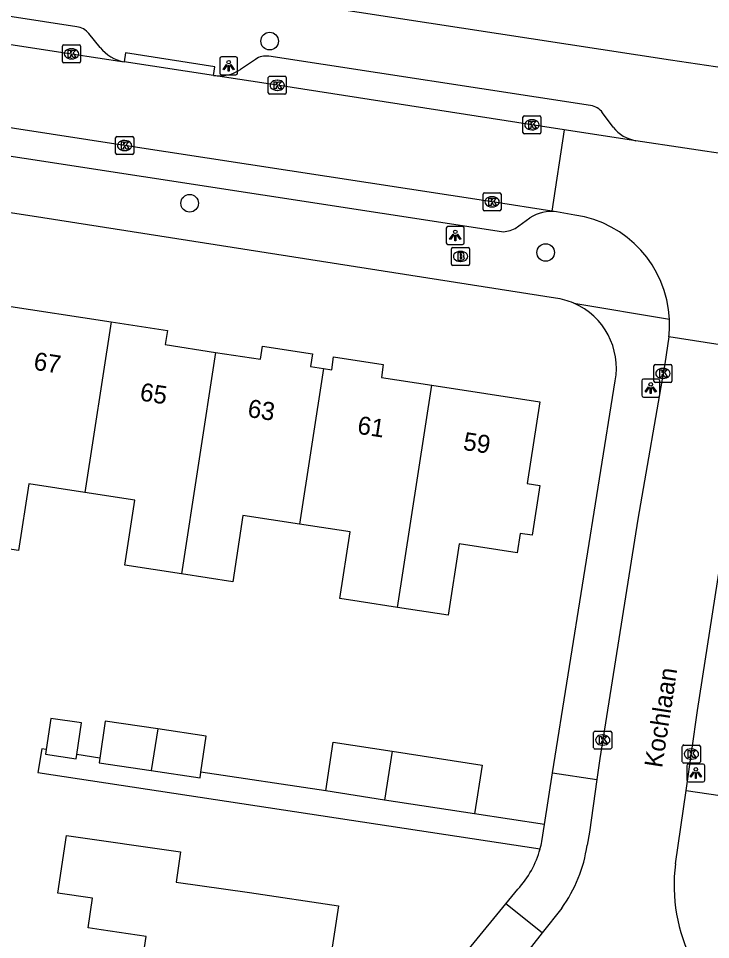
# Model space of a CAD drawing. Extents: x 161486 to 162249, y 379484 to 380829.
# Drawn here: x 161884.6 to 161923, y 380504.4 to 380555.5 of the extents above; entities that cross this region are included whole.
import ezdxf

# ---------------------------------------------------------------- set-up
doc = ezdxf.new("R2010")
doc.units = 0
for name, color, linetype in [('IMGEO_Boom', 7, 'Continuous'), ('IMGEO_Brandkraan', 7, 'Continuous'), ('IMGEO_Kolk', 7, 'Continuous'), ('IMGEO_Lichtpunt', 7, 'Continuous'), ('IMGEO_Openbare_ruimte_label', 7, 'Continuous'), ('IMGEO_Pand', 7, 'Continuous'), ('IMGEO_Pand_nummerreeks', 7, 'Continuous'), ('IMGEO_Rijbaan_lokaal_open', 7, 'Continuous'), ('IMGEO_Voetpad_open', 7, 'Continuous')]:
    doc.layers.add(name, color=color, linetype=linetype)

msp = doc.modelspace()

# ---------------------------------------------------------------- linework, layer by layer
at = {"layer": 'IMGEO_Boom'}
for centre in [(161898.494, 380554.242), (161894.054, 380545.25), (161913.812, 380542.518)]:
    msp.add_circle(centre, 0.489, dxfattribs=at)
at = {"layer": 'IMGEO_Brandkraan'}
for p, q in [((161908.589, 380541.876), (161908.589, 380542.728)), ((161908.664, 380542.802), (161909.516, 380542.802)), ((161909.077, 380542.582), (161909.102, 380542.582)), ((161909.59, 380542.728), (161909.59, 380541.876)), ((161909.516, 380541.802), (161908.664, 380541.802)), ((161909.1, 380542.022), (161909.075, 380542.022))]:
    msp.add_line(p, q, dxfattribs=at)
for points in [[(161908.589, 380541.876), (161908.589, 380542.728)], [(161908.664, 380542.802), (161909.516, 380542.802)], [(161909.59, 380542.728), (161909.59, 380541.876)], [(161908.937, 380542.502), (161908.937, 380542.102), (161909.15, 380542.102)], [(161909.168, 380542.502), (161908.937, 380542.502)], [(161909.116, 380542.421), (161909.062, 380542.421), (161909.062, 380542.345)], [(161909.062, 380542.345), (161909.115, 380542.345)], [(161909.124, 380542.269), (161909.062, 380542.269), (161909.062, 380542.188)], [(161909.062, 380542.188), (161909.124, 380542.188)], [(161909.516, 380541.802), (161908.664, 380541.802)]]:
    msp.add_lwpolyline(points, dxfattribs=at)
for centre, radius, start, end in [((161908.666, 380542.726), 0.0765, 91.552, 178.448), ((161908.666, 380542.726), 0.0765, 91.552, 178.448), ((161909.514, 380542.726), 0.0765, 1.552, 88.448), ((161909.514, 380542.726), 0.0765, 1.552, 88.448), ((161909.117, 380542.383), 0.0379, 267.8285, 90.9355), ((161909.125, 380542.228), 0.0404, 269.8759, 90.5077), ((161909.156, 380542.353), 0.251, 268.6676, 293.5347), ((161909.172, 380542.357), 0.145, 59.4692, 91.5367), ((161909.197, 380542.404), 0.0922, 285.5137, 58.1501), ((161909.202, 380542.212), 0.105, 301.3115, 78.989), ((161908.666, 380541.878), 0.0765, 181.552, 268.448), ((161908.666, 380541.878), 0.0765, 181.552, 268.448), ((161909.514, 380541.878), 0.0765, 271.552, 358.448), ((161909.514, 380541.878), 0.0765, 271.552, 358.448)]:
    msp.add_arc(centre, radius, start, end, dxfattribs=at)
for centre, major_axis, ratio, start_param, end_param in [((161909.076, 380542.302), (-0.387, 0.002), 0.722429, 4.712389, 7.853982), ((161909.101, 380542.302), (-0.39, 0.002), 0.717154, 1.570796, 4.712389)]:
    msp.add_ellipse(centre, major_axis=major_axis, ratio=ratio, start_param=start_param, end_param=end_param, dxfattribs=at)
at = {"layer": 'IMGEO_Kolk'}
for p, q in [((161886.998, 380553.111), (161886.998, 380553.963)), ((161887.073, 380554.037), (161887.925, 380554.037)), ((161887.486, 380553.817), (161887.511, 380553.817)), ((161887.999, 380553.963), (161887.999, 380553.111)), ((161887.925, 380553.037), (161887.073, 380553.037)), ((161887.509, 380553.257), (161887.484, 380553.257)), ((161898.493, 380552.292), (161899.345, 380552.292)), ((161898.418, 380551.366), (161898.418, 380552.218)), ((161898.906, 380552.072), (161898.931, 380552.072)), ((161899.419, 380552.218), (161899.419, 380551.366)), ((161899.345, 380551.292), (161898.493, 380551.292)), ((161898.929, 380551.512), (161898.904, 380551.512)), ((161912.551, 380549.175), (161912.551, 380550.027)), ((161912.626, 380550.101), (161913.478, 380550.101)), ((161913.039, 380549.881), (161913.064, 380549.881)), ((161913.552, 380550.027), (161913.552, 380549.175)), ((161913.062, 380549.321), (161913.037, 380549.321)), ((161889.947, 380548.025), (161889.947, 380548.877)), ((161890.022, 380548.951), (161890.874, 380548.951)), ((161890.435, 380548.731), (161890.46, 380548.731)), ((161890.948, 380548.877), (161890.948, 380548.025)), ((161913.478, 380549.101), (161912.626, 380549.101)), ((161890.458, 380548.171), (161890.433, 380548.171)), ((161890.874, 380547.951), (161890.022, 380547.951)), ((161910.336, 380544.903), (161910.336, 380545.755)), ((161910.411, 380545.829), (161911.263, 380545.829)), ((161911.337, 380545.755), (161911.337, 380544.903)), ((161910.824, 380545.609), (161910.849, 380545.609)), ((161911.263, 380544.829), (161910.411, 380544.829)), ((161910.847, 380545.049), (161910.822, 380545.049)), ((161919.822, 380535.384), (161919.822, 380536.236)), ((161919.897, 380536.31), (161920.749, 380536.31)), ((161920.31, 380536.09), (161920.335, 380536.09)), ((161920.823, 380536.236), (161920.823, 380535.384)), ((161920.333, 380535.53), (161920.308, 380535.53)), ((161920.749, 380535.31), (161919.897, 380535.31)), ((161916.477, 380515.053), (161916.477, 380515.905)), ((161916.552, 380515.979), (161917.404, 380515.979)), ((161916.965, 380515.759), (161916.99, 380515.759)), ((161917.478, 380515.905), (161917.478, 380515.053)), ((161917.404, 380514.979), (161916.552, 380514.979)), ((161916.988, 380515.199), (161916.963, 380515.199)), ((161921.398, 380514.277), (161921.398, 380515.129)), ((161921.473, 380515.203), (161922.325, 380515.203)), ((161921.886, 380514.983), (161921.911, 380514.983)), ((161922.399, 380515.129), (161922.399, 380514.277)), ((161922.325, 380514.203), (161921.473, 380514.203)), ((161921.909, 380514.423), (161921.884, 380514.423))]:
    msp.add_line(p, q, dxfattribs=at)
for points in [[(161886.998, 380553.111), (161886.998, 380553.963)], [(161887.073, 380554.037), (161887.925, 380554.037)], [(161887.999, 380553.963), (161887.999, 380553.111)], [(161887.319, 380553.737), (161887.442, 380553.737), (161887.442, 380553.586), (161887.572, 380553.737), (161887.736, 380553.737), (161887.59, 380553.586), (161887.743, 380553.337), (161887.591, 380553.337), (161887.506, 380553.501), (161887.442, 380553.434), (161887.442, 380553.337), (161887.319, 380553.337), (161887.319, 380553.737)], [(161887.925, 380553.037), (161887.073, 380553.037)], [(161898.493, 380552.292), (161899.345, 380552.292)], [(161898.418, 380551.366), (161898.418, 380552.218)], [(161898.739, 380551.992), (161898.862, 380551.992), (161898.862, 380551.841), (161898.992, 380551.992), (161899.156, 380551.992), (161899.01, 380551.841), (161899.163, 380551.592), (161899.011, 380551.592), (161898.926, 380551.756), (161898.862, 380551.689), (161898.862, 380551.592), (161898.739, 380551.592), (161898.739, 380551.992)], [(161899.419, 380552.218), (161899.419, 380551.366)], [(161899.345, 380551.292), (161898.493, 380551.292)], [(161912.551, 380549.175), (161912.551, 380550.027)], [(161912.626, 380550.101), (161913.478, 380550.101)], [(161912.872, 380549.801), (161912.995, 380549.801), (161912.995, 380549.65), (161913.125, 380549.801), (161913.289, 380549.801), (161913.143, 380549.65), (161913.296, 380549.401), (161913.144, 380549.401), (161913.059, 380549.565), (161912.995, 380549.498), (161912.995, 380549.401), (161912.872, 380549.401), (161912.872, 380549.801)], [(161913.552, 380550.027), (161913.552, 380549.175)], [(161889.947, 380548.025), (161889.947, 380548.877)], [(161890.022, 380548.951), (161890.874, 380548.951)], [(161890.948, 380548.877), (161890.948, 380548.025)], [(161913.478, 380549.101), (161912.626, 380549.101)], [(161890.268, 380548.651), (161890.391, 380548.651), (161890.391, 380548.5), (161890.521, 380548.651), (161890.685, 380548.651), (161890.539, 380548.5), (161890.692, 380548.251), (161890.54, 380548.251), (161890.455, 380548.415), (161890.391, 380548.348), (161890.391, 380548.251), (161890.268, 380548.251), (161890.268, 380548.651)], [(161890.874, 380547.951), (161890.022, 380547.951)], [(161910.336, 380544.903), (161910.336, 380545.755)], [(161910.411, 380545.829), (161911.263, 380545.829)], [(161911.337, 380545.755), (161911.337, 380544.903)], [(161910.657, 380545.529), (161910.78, 380545.529), (161910.78, 380545.378), (161910.91, 380545.529), (161911.074, 380545.529), (161910.928, 380545.378), (161911.081, 380545.129), (161910.929, 380545.129), (161910.844, 380545.293), (161910.78, 380545.226), (161910.78, 380545.129), (161910.657, 380545.129), (161910.657, 380545.529)], [(161911.263, 380544.829), (161910.411, 380544.829)], [(161919.822, 380535.384), (161919.822, 380536.236)], [(161919.897, 380536.31), (161920.749, 380536.31)], [(161920.143, 380536.01), (161920.266, 380536.01), (161920.266, 380535.859), (161920.396, 380536.01), (161920.56, 380536.01), (161920.414, 380535.859), (161920.567, 380535.61), (161920.415, 380535.61), (161920.33, 380535.774), (161920.266, 380535.707), (161920.266, 380535.61), (161920.143, 380535.61), (161920.143, 380536.01)], [(161920.823, 380536.236), (161920.823, 380535.384)], [(161920.749, 380535.31), (161919.897, 380535.31)], [(161916.477, 380515.053), (161916.477, 380515.905)], [(161916.552, 380515.979), (161917.404, 380515.979)], [(161916.798, 380515.679), (161916.921, 380515.679), (161916.921, 380515.528), (161917.051, 380515.679), (161917.215, 380515.679), (161917.069, 380515.528), (161917.222, 380515.279), (161917.07, 380515.279), (161916.985, 380515.443), (161916.921, 380515.376), (161916.921, 380515.279), (161916.798, 380515.279), (161916.798, 380515.679)], [(161917.478, 380515.905), (161917.478, 380515.053)], [(161917.404, 380514.979), (161916.552, 380514.979)], [(161921.398, 380514.277), (161921.398, 380515.129)], [(161921.473, 380515.203), (161922.325, 380515.203)], [(161922.399, 380515.129), (161922.399, 380514.277)], [(161921.719, 380514.903), (161921.842, 380514.903), (161921.842, 380514.752), (161921.972, 380514.903), (161922.136, 380514.903), (161921.99, 380514.752), (161922.143, 380514.503), (161921.991, 380514.503), (161921.906, 380514.667), (161921.842, 380514.6), (161921.842, 380514.503), (161921.719, 380514.503), (161921.719, 380514.903)], [(161922.325, 380514.203), (161921.473, 380514.203)]]:
    msp.add_lwpolyline(points, dxfattribs=at)
for centre, start, end in [((161887.075, 380553.961), 91.552, 178.448), ((161887.075, 380553.961), 91.552, 178.448), ((161887.923, 380553.961), 1.552, 88.448), ((161887.923, 380553.961), 1.552, 88.448), ((161887.075, 380553.113), 181.552, 268.448), ((161887.075, 380553.113), 181.552, 268.448), ((161887.923, 380553.113), 271.552, 358.448), ((161887.923, 380553.113), 271.552, 358.448), ((161898.495, 380552.216), 91.552, 178.448), ((161898.495, 380552.216), 91.552, 178.448), ((161899.343, 380552.216), 1.552, 88.448), ((161899.343, 380552.216), 1.552, 88.448), ((161898.495, 380551.368), 181.552, 268.448), ((161898.495, 380551.368), 181.552, 268.448), ((161899.343, 380551.368), 271.552, 358.448), ((161899.343, 380551.368), 271.552, 358.448), ((161912.628, 380550.025), 91.552, 178.448), ((161912.628, 380550.025), 91.552, 178.448), ((161913.476, 380550.025), 1.552, 88.448), ((161913.476, 380550.025), 1.552, 88.448), ((161890.024, 380548.875), 91.552, 178.448), ((161890.024, 380548.875), 91.552, 178.448), ((161890.872, 380548.875), 1.552, 88.448), ((161890.872, 380548.875), 1.552, 88.448), ((161912.628, 380549.177), 181.552, 268.448), ((161912.628, 380549.177), 181.552, 268.448), ((161913.476, 380549.177), 271.552, 358.448), ((161913.476, 380549.177), 271.552, 358.448), ((161890.024, 380548.027), 181.552, 268.448), ((161890.024, 380548.027), 181.552, 268.448), ((161890.872, 380548.027), 271.552, 358.448), ((161890.872, 380548.027), 271.552, 358.448), ((161910.413, 380545.753), 91.552, 178.448), ((161910.413, 380545.753), 91.552, 178.448), ((161911.261, 380545.753), 1.552, 88.448), ((161911.261, 380545.753), 1.552, 88.448), ((161910.413, 380544.905), 181.552, 268.448), ((161910.413, 380544.905), 181.552, 268.448), ((161911.261, 380544.905), 271.552, 358.448), ((161911.261, 380544.905), 271.552, 358.448), ((161919.899, 380536.234), 91.552, 178.448), ((161919.899, 380536.234), 91.552, 178.448), ((161920.747, 380536.234), 1.552, 88.448), ((161920.747, 380536.234), 1.552, 88.448), ((161919.899, 380535.386), 181.552, 268.448), ((161919.899, 380535.386), 181.552, 268.448), ((161920.747, 380535.386), 271.552, 358.448), ((161920.747, 380535.386), 271.552, 358.448), ((161916.554, 380515.903), 91.552, 178.448), ((161916.554, 380515.903), 91.552, 178.448), ((161917.402, 380515.903), 1.552, 88.448), ((161917.402, 380515.903), 1.552, 88.448), ((161916.554, 380515.055), 181.552, 268.448), ((161916.554, 380515.055), 181.552, 268.448), ((161917.402, 380515.055), 271.552, 358.448), ((161917.402, 380515.055), 271.552, 358.448), ((161921.475, 380515.127), 91.552, 178.448), ((161921.475, 380515.127), 91.552, 178.448), ((161922.323, 380515.127), 1.552, 88.448), ((161922.323, 380515.127), 1.552, 88.448), ((161921.475, 380514.279), 181.552, 268.448), ((161921.475, 380514.279), 181.552, 268.448), ((161922.323, 380514.279), 271.552, 358.448), ((161922.323, 380514.279), 271.552, 358.448)]:
    msp.add_arc(centre, 0.0765, start, end, dxfattribs=at)
for centre, major_axis, ratio, start_param, end_param in [((161887.485, 380553.537), (-0.387, 0.002), 0.722429, 4.712389, 7.853982), ((161887.51, 380553.537), (-0.39, 0.002), 0.717154, 1.570796, 4.712389), ((161898.905, 380551.792), (-0.387, 0.002), 0.722429, 4.712389, 7.853982), ((161898.93, 380551.792), (-0.39, 0.002), 0.717154, 1.570796, 4.712389), ((161913.038, 380549.601), (-0.387, 0.002), 0.722429, 4.712389, 7.853982), ((161913.063, 380549.601), (-0.39, 0.002), 0.717154, 1.570796, 4.712389), ((161890.434, 380548.451), (-0.387, 0.002), 0.722429, 4.712389, 7.853982), ((161890.459, 380548.451), (-0.39, 0.002), 0.717154, 1.570796, 4.712389), ((161910.823, 380545.329), (-0.387, 0.002), 0.722429, 4.712389, 7.853982), ((161910.848, 380545.329), (-0.39, 0.002), 0.717154, 1.570796, 4.712389), ((161920.309, 380535.81), (-0.387, 0.002), 0.722429, 4.712389, 7.853982), ((161920.334, 380535.81), (-0.39, 0.002), 0.717154, 1.570796, 4.712389), ((161916.964, 380515.479), (-0.387, 0.002), 0.722429, 4.712389, 7.853982), ((161916.989, 380515.479), (-0.39, 0.002), 0.717154, 1.570796, 4.712389), ((161921.885, 380514.703), (-0.387, 0.002), 0.722429, 4.712389, 7.853982), ((161921.91, 380514.703), (-0.39, 0.002), 0.717154, 1.570796, 4.712389)]:
    msp.add_ellipse(centre, major_axis=major_axis, ratio=ratio, start_param=start_param, end_param=end_param, dxfattribs=at)
at = {"layer": 'IMGEO_Lichtpunt'}
for p, q in [((161896.625, 380553.37), (161895.817, 380553.37)), ((161896.625, 380553.37), (161895.817, 380553.37)), ((161895.723, 380553.275), (161895.723, 380552.468)), ((161895.723, 380553.275), (161895.723, 380552.468)), ((161896.719, 380552.468), (161896.719, 380553.275)), ((161896.719, 380552.468), (161896.719, 380553.275)), ((161895.817, 380552.374), (161896.625, 380552.374)), ((161895.817, 380552.374), (161896.625, 380552.374)), ((161908.298, 380543.865), (161908.298, 380543.058)), ((161908.298, 380543.865), (161908.298, 380543.058)), ((161909.2, 380543.96), (161908.392, 380543.96)), ((161909.2, 380543.96), (161908.392, 380543.96)), ((161909.294, 380543.058), (161909.294, 380543.865)), ((161909.294, 380543.058), (161909.294, 380543.865)), ((161908.392, 380542.964), (161909.2, 380542.964)), ((161908.392, 380542.964), (161909.2, 380542.964)), ((161919.146, 380535.405), (161919.146, 380534.598)), ((161919.146, 380535.405), (161919.146, 380534.598)), ((161920.048, 380535.5), (161919.24, 380535.5)), ((161920.048, 380535.5), (161919.24, 380535.5)), ((161920.142, 380534.598), (161920.142, 380535.405)), ((161920.142, 380534.598), (161920.142, 380535.405)), ((161919.24, 380534.504), (161920.048, 380534.504)), ((161919.24, 380534.504), (161920.048, 380534.504)), ((161921.647, 380514.053), (161921.647, 380513.246)), ((161921.647, 380514.053), (161921.647, 380513.246)), ((161922.549, 380514.148), (161921.741, 380514.148)), ((161922.549, 380514.148), (161921.741, 380514.148)), ((161922.643, 380513.246), (161922.643, 380514.053)), ((161922.643, 380513.246), (161922.643, 380514.053)), ((161921.741, 380513.152), (161922.549, 380513.152)), ((161921.741, 380513.152), (161922.549, 380513.152))]:
    msp.add_line(p, q, dxfattribs=at)
for points in [[(161896.097, 380552.939), (161896.136, 380552.911), (161895.948, 380552.649), (161895.91, 380552.676), (161896.097, 380552.939)], [(161896.199, 380552.891), (161896.246, 380552.891), (161896.246, 380552.569), (161896.199, 380552.569), (161896.199, 380552.891)], [(161896.309, 380552.911), (161896.347, 380552.938), (161896.534, 380552.676), (161896.495, 380552.648), (161896.309, 380552.911)], [(161908.672, 380543.529), (161908.711, 380543.501), (161908.523, 380543.239), (161908.485, 380543.266), (161908.672, 380543.529)], [(161908.774, 380543.481), (161908.821, 380543.481), (161908.821, 380543.159), (161908.774, 380543.159), (161908.774, 380543.481)], [(161908.884, 380543.501), (161908.922, 380543.528), (161909.109, 380543.266), (161909.07, 380543.238), (161908.884, 380543.501)], [(161919.52, 380535.069), (161919.559, 380535.041), (161919.371, 380534.779), (161919.333, 380534.806), (161919.52, 380535.069)], [(161919.622, 380535.021), (161919.669, 380535.021), (161919.669, 380534.699), (161919.622, 380534.699), (161919.622, 380535.021)], [(161919.732, 380535.041), (161919.77, 380535.068), (161919.957, 380534.806), (161919.918, 380534.778), (161919.732, 380535.041)], [(161922.021, 380513.717), (161922.06, 380513.689), (161921.872, 380513.427), (161921.834, 380513.454), (161922.021, 380513.717)], [(161922.123, 380513.669), (161922.17, 380513.669), (161922.17, 380513.347), (161922.123, 380513.347), (161922.123, 380513.669)], [(161922.233, 380513.689), (161922.271, 380513.716), (161922.458, 380513.454), (161922.419, 380513.426), (161922.233, 380513.689)]]:
    msp.add_lwpolyline(points, dxfattribs=at)
for centre in [(161896.222, 380553.073), (161908.797, 380543.663), (161919.645, 380535.203), (161922.146, 380513.851)]:
    msp.add_circle(centre, 0.0994, dxfattribs=at)
for centre, start, end in [((161895.817, 380553.275), 90, 180), ((161895.817, 380553.275), 90, 180), ((161896.625, 380553.275), 0, 90), ((161896.625, 380553.275), 0, 90), ((161895.817, 380552.468), 180, 270), ((161895.817, 380552.468), 180, 270), ((161896.625, 380552.468), 270, 0), ((161896.625, 380552.468), 270, 360), ((161908.392, 380543.865), 90, 180), ((161908.392, 380543.865), 90, 180), ((161909.2, 380543.865), 0, 90), ((161909.2, 380543.865), 0, 90), ((161908.392, 380543.058), 180, 270), ((161908.392, 380543.058), 180, 270), ((161909.2, 380543.058), 270, 0), ((161909.2, 380543.058), 270, 360), ((161919.24, 380535.405), 90, 180), ((161919.24, 380535.405), 90, 180), ((161920.048, 380535.405), 0, 90), ((161920.048, 380535.405), 0, 90), ((161919.24, 380534.598), 180, 270), ((161919.24, 380534.598), 180, 270), ((161920.048, 380534.598), 270, 0), ((161920.048, 380534.598), 270, 360), ((161921.741, 380514.053), 90, 180), ((161921.741, 380514.053), 90, 180), ((161922.549, 380514.053), 0, 90), ((161922.549, 380514.053), 0, 90), ((161921.741, 380513.246), 180, 270), ((161921.741, 380513.246), 180, 270), ((161922.549, 380513.246), 270, 0), ((161922.549, 380513.246), 270, 360)]:
    msp.add_arc(centre, 0.0946, start, end, dxfattribs=at)
at = {"layer": 'IMGEO_Pand'}
for points in [[(161883.646, 380539.603), (161889.692, 380538.674)], [(161889.692, 380538.674), (161888.236, 380529.203)], [(161889.692, 380538.674), (161892.825, 380538.192), (161892.705, 380537.408), (161895.495, 380536.979)], [(161895.495, 380536.979), (161893.606, 380524.696)], [(161895.495, 380536.979), (161897.993, 380536.595), (161898.106, 380537.327), (161900.867, 380536.903), (161900.758, 380536.196), (161901.484, 380536.085)], [(161901.484, 380536.085), (161901.937, 380536.015), (161902.047, 380536.731), (161904.802, 380536.307), (161904.693, 380535.594), (161907.492, 380535.164)], [(161901.484, 380536.085), (161900.156, 380527.45)], [(161907.492, 380535.164), (161913.491, 380534.241), (161912.794, 380529.703), (161913.496, 380529.595), (161913.072, 380526.838), (161912.396, 380526.942), (161912.231, 380525.867), (161909.007, 380526.362), (161908.397, 380522.398), (161905.595, 380522.829)], [(161905.595, 380522.829), (161907.492, 380535.164)], [(161888.236, 380529.203), (161885.124, 380529.681), (161884.557, 380525.991), (161881.622, 380526.442), (161882.189, 380530.131)], [(161893.606, 380524.696), (161890.453, 380525.181), (161891.006, 380528.777), (161888.236, 380529.203)], [(161900.156, 380527.45), (161897.01, 380527.933), (161896.446, 380524.26), (161893.606, 380524.696)], [(161905.595, 380522.829), (161903.456, 380523.158), (161902.389, 380523.322), (161902.958, 380527.019), (161900.156, 380527.45)], [(161887.792, 380514.675), (161888.05, 380516.432), (161886.348, 380516.682), (161886.094, 380514.947)], [(161892.283, 380516.095), (161889.363, 380516.524), (161889.062, 380514.472)], [(161892.283, 380516.095), (161891.928, 380513.785)], [(161894.679, 380513.703), (161894.973, 380515.7), (161892.283, 380516.095)], [(161901.608, 380512.653), (161902.025, 380515.359), (161905.289, 380514.856)], [(161886.094, 380514.947), (161886.056, 380514.688), (161887.757, 380514.438), (161887.792, 380514.675)], [(161889.062, 380514.472), (161889.024, 380514.212), (161891.928, 380513.785)], [(161905.289, 380514.856), (161904.874, 380512.15)], [(161905.289, 380514.856), (161910.287, 380514.087), (161909.87, 380511.381)], [(161891.928, 380513.785), (161894.633, 380513.388), (161894.679, 380513.703)], [(161904.874, 380512.15), (161901.608, 380512.653)], [(161909.87, 380511.381), (161904.874, 380512.15)], [(161891.087, 380500.923), (161891.637, 380504.58), (161889.15, 380504.959), (161888.417, 380505.064), (161888.668, 380506.71), (161886.742, 380506.985), (161887.229, 380510.177), (161893.554, 380509.272), (161893.313, 380507.589), (161897.375, 380507.031), (161902.318, 380506.279), (161901.363, 380500), (161901.267, 380499.372)]]:
    msp.add_lwpolyline(points, dxfattribs=at)
at = {"layer": 'IMGEO_Rijbaan_lokaal_open'}
for points in [[(161849.846, 380559.342), (161887.499, 380553.536), (161890.424, 380553.087)], [(161914.156, 380544.809), (161910.838, 380545.329), (161890.447, 380548.452), (161871.858, 380551.32), (161849.159, 380554.782)], [(161895.38, 380552.327), (161890.424, 380553.087)], [(161914.845, 380549.326), (161913.052, 380549.6), (161898.919, 380551.791), (161895.38, 380552.327)], [(161914.845, 380549.326), (161914.156, 380544.809)], [(161918.825, 380548.717), (161914.845, 380549.326)], [(161929.69, 380547.086), (161918.825, 380548.717)], [(161914.419, 380544.768), (161914.156, 380544.809)], [(161915.431, 380544.596), (161914.419, 380544.768)], [(161920.649, 380537.844), (161920.428, 380536.339), (161918.926, 380527.722), (161916.815, 380514.45), (161916.654, 380513.285)], [(161925.521, 380537.092), (161920.649, 380537.844)], [(161921.604, 380512.685), (161922.248, 380517.116), (161924.453, 380531.388), (161925.192, 380535.036), (161925.521, 380537.092)], [(161916.654, 380513.285), (161916.253, 380510.374), (161916.11, 380509.645)], [(161921.012, 380508.607), (161921.604, 380512.685)], [(161914.711, 380506.156), (161913.613, 380504.779)], [(161913.613, 380504.779), (161913.02, 380504.036), (161909.582, 380500), (161909.249, 380499.609)]]:
    msp.add_lwpolyline(points, dxfattribs=at)
for centre, radius, start, end in [((161914.556, 380538.527), 6.131, 2.7628, 81.7935), ((161914.529, 380538.528), 6.158, 353.6247, 2.748), ((161908.389, 380510.716), 7.795, 324.198, 352.1029), ((161930.315, 380507.442), 9.376, 172.8619, 207.0106)]:
    msp.add_arc(centre, radius, start, end, dxfattribs=at)
at = {"layer": 'IMGEO_Voetpad_open'}
for points in [[(161842.113, 380565.304), (161845.302, 380564.812), (161850.616, 380563.993), (161887.994, 380558.235), (161920.738, 380553.21), (161923.744, 380552.759)], [(161887.795, 380555.038), (161850.1, 380560.875), (161846.172, 380561.483)], [(161889.081, 380553.896), (161888.457, 380554.66)], [(161895.38, 380552.327), (161895.456, 380552.821), (161890.502, 380553.592), (161890.424, 380553.087)], [(161916.305, 380550.672), (161898.45, 380553.401)], [(161851.745, 380552.829), (161911.363, 380543.674)], [(161897.708, 380553.23), (161896.882, 380552.673)], [(161917.56, 380549.474), (161916.972, 380550.271)], [(161914.351, 380539.988), (161885.9, 380544.447), (161848.674, 380550.183)], [(161912.118, 380543.856), (161912.933, 380544.438)], [(161915.374, 380539.705), (161920.68, 380538.823)], [(161914.189, 380513.654), (161917.669, 380535.395)], [(161886.094, 380514.947), (161885.86, 380514.984), (161885.626, 380513.687), (161913.506, 380509.44)], [(161889.062, 380514.472), (161887.792, 380514.675)], [(161901.608, 380512.653), (161894.679, 380513.703)], [(161913.747, 380510.794), (161914.189, 380513.654)], [(161914.189, 380513.654), (161916.654, 380513.285)], [(161921.604, 380512.685), (161924.124, 380512.314)], [(161913.747, 380510.794), (161909.87, 380511.381)], [(161913.602, 380509.851), (161913.747, 380510.794)], [(161911.601, 380506.388), (161912.268, 380507.199)], [(161906.568, 380500), (161907.579, 380501.499), (161911.601, 380506.388)], [(161913.613, 380504.779), (161911.601, 380506.388)]]:
    msp.add_lwpolyline(points, dxfattribs=at)
for centre, radius, start, end in [((161887.677, 380554.063), 0.982, 37.4245, 83.123), ((161890.815, 380555.255), 2.202, 218.0859, 259.7861), ((161898.286, 380552.416), 0.998, 80.5618, 125.3936), ((161895.665, 380554.522), 2.213, 262.5942, 303.3505), ((161916.139, 380549.64), 1.045, 37.1342, 80.8373), ((161919.169, 380550.727), 2.039, 217.9118, 260.294), ((161914.118, 380542.611), 2.178, 82.0662, 122.9751), ((161911.422, 380545.085), 1.412, 267.588, 299.5183), ((161913.818, 380536.071), 3.953, 66.8217, 82.2514), ((161913.828, 380536.116), 3.908, 349.3749, 66.6941), ((161908.147, 380510.908), 5.556, 344.6762, 349.0294), ((161908.259, 380510.876), 5.44, 317.4726, 344.692)]:
    msp.add_arc(centre, radius, start, end, dxfattribs=at)

# ---------------------------------------------------------------- texts
at = {"layer": 'IMGEO_Openbare_ruimte_label'}
msp.add_text('Kochlaan', height=1, rotation=81.1972, dxfattribs=at).set_placement((161920.272, 380513.899))
at = {"layer": 'IMGEO_Pand_nummerreeks'}
for s, rotation, p in [('67', 351.2624, (161885.353, 380536.022)), ('65', 351.3268, (161891.25, 380534.316)), ('63', 351.3268, (161897.23, 380533.404)), ('61', 351.3268, (161903.321, 380532.474)), ('59', 351.3268, (161909.19, 380531.579))]:
    msp.add_text(s, height=1, rotation=rotation, dxfattribs=at).set_placement(p)

doc.saveas('drawing.dxf')
